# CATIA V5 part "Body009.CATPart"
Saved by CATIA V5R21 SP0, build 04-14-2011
Part number: Body009
Definition: design
Nomenclature: Body009
Source: Unknown
Bounding box of the stored display mesh (mm): x -0.8 to 0.8, y -1.3 to 1.3, z 0 to 0.1
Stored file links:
  C:\Users\beatr\OneDrive\Documents\UNB\2026_1\Pi1\Componentes eletronicos\Encoder\Body009.CATPart
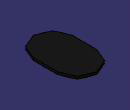
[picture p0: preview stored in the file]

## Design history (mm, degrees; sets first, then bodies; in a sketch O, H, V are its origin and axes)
Body1 "MANIFOLD_SOLID_BREP #4858" (main body)
  Solid1: solid without history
